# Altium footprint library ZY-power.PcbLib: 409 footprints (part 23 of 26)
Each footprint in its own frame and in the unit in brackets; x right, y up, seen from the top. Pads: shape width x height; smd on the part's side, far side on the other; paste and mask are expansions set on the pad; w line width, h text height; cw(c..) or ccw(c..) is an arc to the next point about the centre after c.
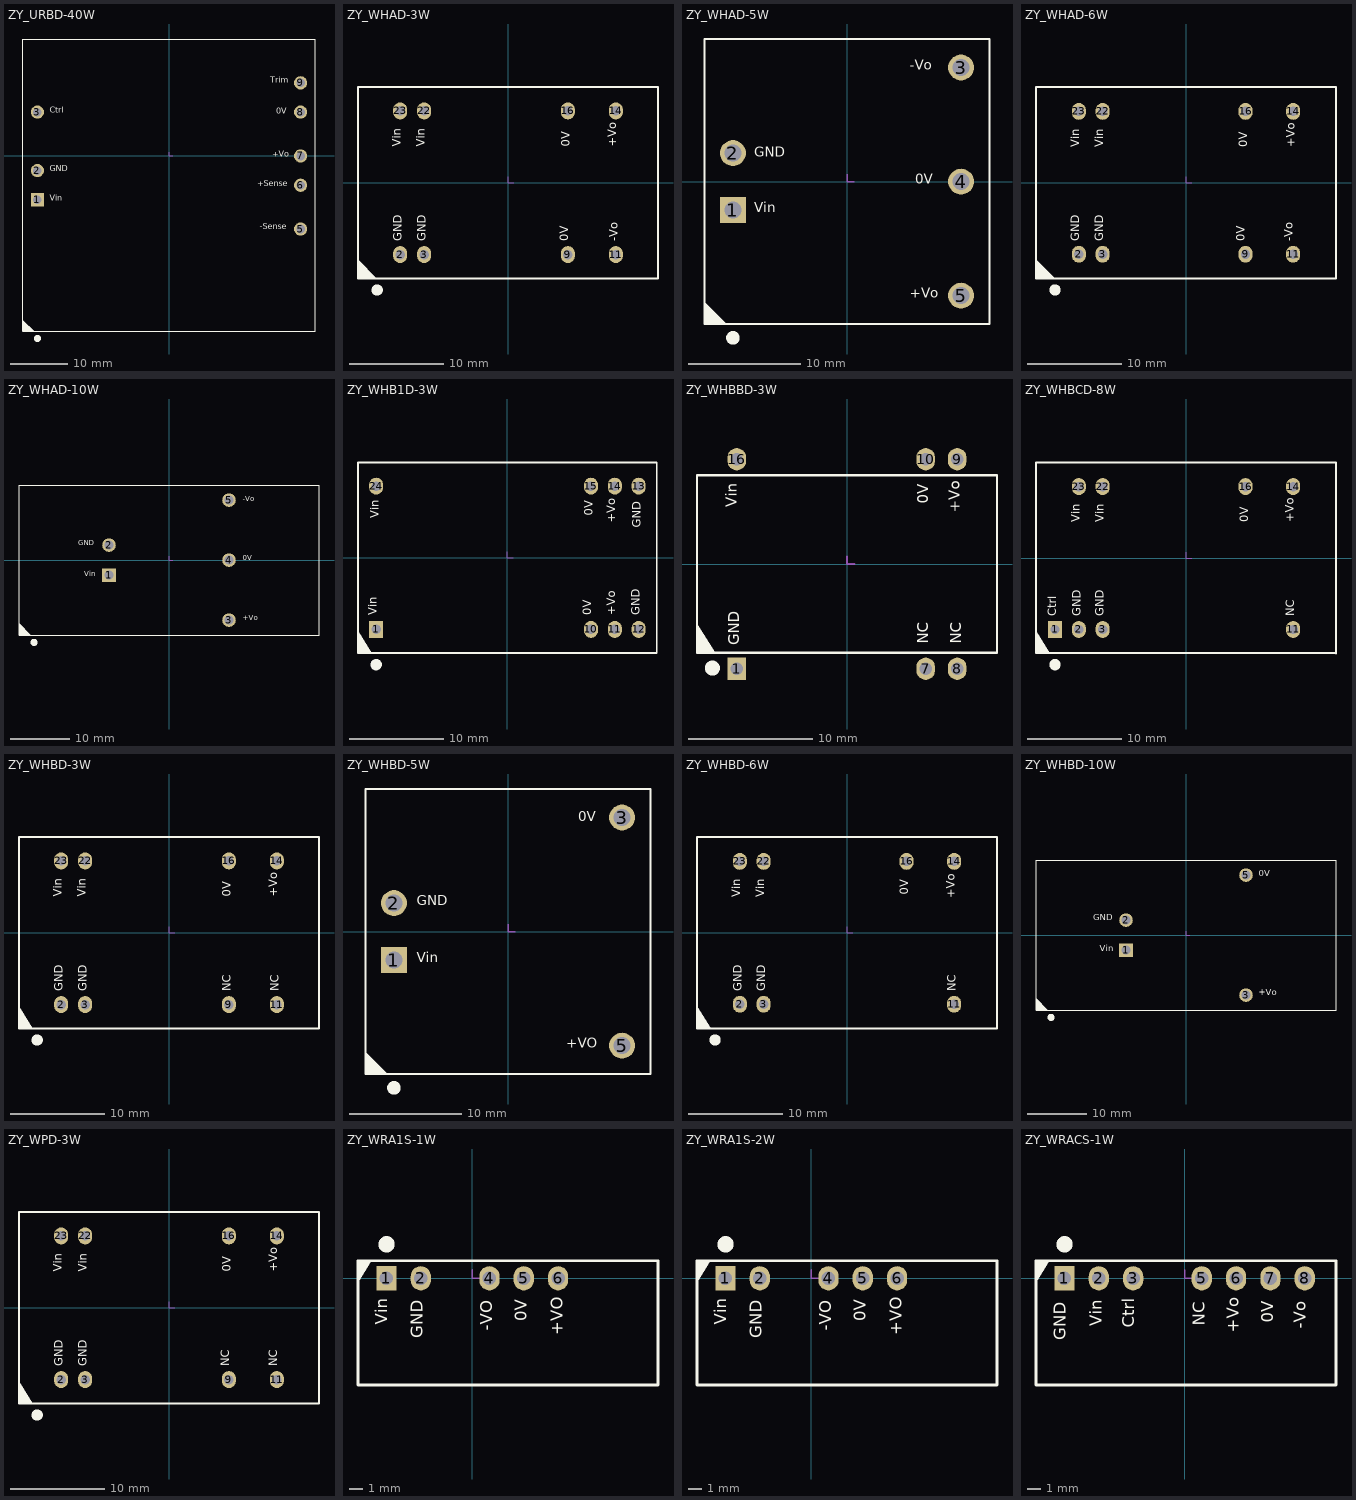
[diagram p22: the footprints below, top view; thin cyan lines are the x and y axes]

## ZY_URBD-40W [mm]
height 13.8
pads (8):
  rect 2.3x2.3 hole 1.5: 1(-22.86,-7.62)
  round 2.3 hole 1.5: 2(-22.86,-2.54) 3(-22.86,7.62) 5(22.86,-12.7) 6(22.86,-5.08) 7(22.86,0) 8(22.86,7.62) 9(22.86,12.7)
Top Overlay:
  circle w1: c-22.86,-31.705 r0.1
  region: -25.4,-30.48 -23.425,-30.48 -25.4,-28.505
  lines w0.2: -25.4,-30.48 -25.4,20.32 25.4,20.32 25.4,-30.48 -25.4,-30.48
  text "-Sense" at 15.731,-13.081 h1.78
  text "GND" at -20.701,-3.028 h1.78
  text "Trim" at 17.614,12.339 h1.78
  text "Ctrl" at -20.701,7.132 h1.78
  text "+Vo" at 17.926,-0.488 h1.78
  text "+Sense" at 15.367,-5.588 h1.78
  text "Vin" at -20.701,-8.108 h1.78
  text "0V" at 18.663,7.005 h1.78
Mechanical 15:
  lines w0.127: 0,0.635 0,0 0.635,0

## ZY_WHAD-3W [mm] "宽压输入隔离稳压双输出电源模块"
height 9.5
pads (8):
  oval 1.5x1.8 hole 1: 2(-11.43,-7.62) 3(-8.89,-7.62) 9(6.35,-7.62) 11(11.43,-7.62) 14(11.43,7.62) 16(6.35,7.62) 22(-8.89,7.62) 23(-11.43,7.62)
Top Overlay:
  circle w1: c-13.87,-11.375 r0.1
  region: -15.9,-10.15 -13.925,-10.15 -15.9,-8.175
  lines w0.2: -15.9,-10.15 15.9,-10.15 15.9,10.15 -15.9,10.15 -15.9,-10.15
  text "Vin" at -11.049,3.81 h1.52
  text "Vin" at -8.509,3.81 h1.52
  text "0V" at 6.858,3.81 h1.52
  text "+Vo" at 11.811,3.81 h1.52
  text "-Vo" at 11.938,-6.223 h1.52
  text "0V" at 6.731,-6.223 h1.52
  text "GND" at -8.382,-6.223 h1.52
  text "GND" at -10.922,-6.223 h1.52
Mechanical 15:
  lines w0.127: 0,0.635 0,0 0.635,0

## ZY_WHAD-5W [mm]
height 11.7
pads (5):
  rect 2.3x2.3 hole 1.5: 1(-10.16,-2.54)
  round 2.3 hole 1.5: 2(-10.16,2.54) 3(10.16,10.16) 4(10.16,0) 5(10.16,-10.16)
Top Overlay:
  circle w1: c-10.16,-13.925 r0.1
  region: -12.7,-12.7 -10.725,-12.7 -12.7,-10.725
  lines w0.2: -12.7,-12.7 -12.7,12.7 12.7,12.7 12.7,-12.7 -12.7,-12.7
  text "0V" at 6.096,-0.508 h1.52
  text "GND" at -8.255,1.905 h1.52
  text "Vin" at -8.255,-3.048 h1.52
  text "+Vo" at 5.588,-10.668 h1.52
  text "-Vo" at 5.588,9.652 h1.52
Mechanical 15:
  lines w0.127: 0,0.635 0,0 0.635,0

## ZY_WHAD-6W [mm]
height 10.5
pads (8):
  oval 1.5x1.8 hole 1: 2(-11.43,-7.62) 3(-8.89,-7.62) 9(6.35,-7.62) 11(11.43,-7.62) 14(11.43,7.62) 16(6.35,7.62) 22(-8.89,7.62) 23(-11.43,7.62)
Top Overlay:
  circle w1: c-13.97,-11.425 r0.1
  region: -16,-10.2 -14.025,-10.2 -16,-8.225
  lines w0.2: -16,-10.2 16,-10.2 16,10.2 -16,10.2 -16,-10.2
  text "0V" at 6.858,3.81 h1.52
  text "+Vo" at 11.938,3.81 h1.52
  text "-Vo" at 11.684,-6.223 h1.52
  text "Vin" at -8.509,3.81 h1.52
  text "Vin" at -11.049,3.81 h1.52
  text "GND" at -8.509,-6.223 h1.52
  text "GND" at -11.049,-6.223 h1.52
  text "0V" at 6.604,-6.223 h1.52
Mechanical 15:
  lines w0.127: 0,0.635 0,0 0.635,0

## ZY_WHAD-10W [mm]
pads (5):
  rect 2.3x2.3 hole 1.5: 1(-10.16,-2.54)
  round 2.3 hole 1.5: 2(-10.16,2.54) 3(10.16,-10.16) 4(10.16,0) 5(10.16,10.16)
Top Overlay:
  circle w1: c-22.86,-13.925 r0.1
  region: -25.4,-12.7 -23.425,-12.7 -25.4,-10.725
  lines w0.2: -25.4,-12.7 25.4,-12.7 25.4,12.7 -25.4,12.7 -25.4,-12.7
  text "Vin" at -14.358,-3.048 h1.52
  text "GND" at -15.368,2.159 h1.52
  text "0V" at 12.446,-0.381 h1.52
  text "+Vo" at 12.446,-10.541 h1.52
  text "-Vo" at 12.446,9.652 h1.52
Mechanical 15:
  lines w0.127: 0,0.635 0,0 0.635,0

## ZY_WHB1D-3W [mm]
height 10.5
pads (8):
  rect 1.5x1.8 hole 1: 1(-13.97,-7.62)
  oval 1.5x1.8 hole 1: 10(8.89,-7.62) 11(11.43,-7.62) 12(13.97,-7.62) 13(13.97,7.62) 14(11.43,7.62) 15(8.89,7.62) 24(-13.97,7.62)
Top Overlay:
  circle w1: c-13.97,-11.375 r0.1
  region: -15.9,-7.82 -15.9,-10.15 -14.44,-10.15
  lines w0.2: -15.9,-10.15 -15.9,10.15 15.9,10.15 15.9,-10.15 -15.9,-10.15
  text "GND" at 14.427,-6.096 h1.52
  text "Vin" at -13.36,4.185 h1.52
  text "Vin" at -13.564,-6.096 h1.52
  text "0V" at 9.246,-6.096 h1.52
  text "+Vo" at 11.811,-6.096 h1.52
  text "0V" at 9.423,4.457 h1.52
  text "+Vo" at 11.811,3.717 h1.52
  text "GND" at 14.503,3.175 h1.52
Mechanical 15:
  lines w0.127: 0,0.635 0,0 0.635,0

## ZY_WHBBD-3W [mm]
height 4.6
pads (6):
  rect 1.5x1.8 hole 1: 1(-8.89,-8.45)
  oval 1.5x1.8 hole 1: 7(6.35,-8.45) 8(8.89,-8.45) 9(8.89,8.45) 10(6.35,8.45) 16(-8.89,8.45)
Top Overlay:
  circle w1: c-10.863,-8.4 r0.1
  region: -12.1,-4.845 -12.1,-7.175 -10.64,-7.175
  lines w0.2: -12.1,-7.175 12.1,-7.175 12.1,7.175 -12.1,7.175 -12.1,-7.175
  text "NC" at 9.525,-6.415 h1.52
  text "GND" at -8.382,-6.542 h1.52
  text "Vin" at -8.56,4.597 h1.52
  text "0V" at 6.858,4.869 h1.52
  text "+Vo" at 9.398,4.129 h1.52
  text "NC" at 6.858,-6.415 h1.52
Mechanical 15:
  lines w0.127: 0,0.635 0,0 0.635,0

## ZY_WHBCD-8W [mm]
height 11
pads (8):
  rect 1.5x1.8 hole 1: 1(-13.97,-7.62)
  oval 1.5x1.8 hole 1: 2(-11.43,-7.62) 3(-8.89,-7.62) 11(11.43,-7.62) 14(11.43,7.62) 16(6.35,7.62) 22(-8.89,7.62) 23(-11.43,7.62)
Top Overlay:
  circle w1: c-13.97,-11.375 r0.1
  region: -16,-7.82 -16,-10.15 -14.54,-10.15
  lines w0.2: 16,-10.2 16,10.2 -16,10.2 -16,-10.15 16,-10.15
  text "GND" at -10.897,-6.223 h1.52
  text "+Vo" at 11.811,3.81 h1.52
  text "0V" at 6.985,3.81 h1.52
  text "Ctrl" at -13.538,-6.223 h1.52
  text "NC" at 11.887,-6.223 h1.52
  text "Vin" at -8.433,3.81 h1.52
  text "Vin" at -10.998,3.81 h1.52
  text "GND" at -8.458,-6.223 h1.52
Mechanical 15:
  lines w0.127: 0,0.635 0,0 0.635,0

## ZY_WHBD-3W [mm] "宽压输入隔离稳压单输出电源模块"
height 9.5
pads (8):
  oval 1.5x1.8 hole 1: 2(-11.43,-7.62) 3(-8.89,-7.62) 9(6.35,-7.62) 11(11.43,-7.62) 14(11.43,7.62) 16(6.35,7.62) 22(-8.89,7.62) 23(-11.43,7.62)
Top Overlay:
  circle w1: c-13.97,-11.375 r0.1
  region: -15.9,-7.82 -15.9,-10.15 -14.44,-10.15
  lines w0.2: -15.9,-10.15 15.9,-10.15 15.9,10.15 -15.9,10.15 -15.9,-10.15
  text "+Vo" at 11.811,3.81 h1.52
  text "0V" at 6.858,3.81 h1.52
  text "Vin" at -8.509,3.81 h1.52
  text "Vin" at -11.049,3.81 h1.52
  text "GND" at -8.382,-6.223 h1.52
  text "GND" at -10.922,-6.223 h1.52
  text "NC" at 6.858,-6.223 h1.52
  text "NC" at 11.938,-6.223 h1.52
Mechanical 15:
  lines w0.127: 0,0.635 0,0 0.635,0

## ZY_WHBD-5W [mm]
height 11.7
pads (4):
  rect 2.3x2.3 hole 1.5: 1(-10.16,-2.54)
  round 2.3 hole 1.5: 2(-10.16,2.54) 3(10.16,10.16) 5(10.16,-10.16)
Top Overlay:
  circle w1: c-10.16,-13.925 r0.1
  region: -12.7,-12.7 -10.725,-12.7 -12.7,-10.725
  lines w0.2: -12.7,-12.7 -12.7,12.7 12.7,12.7 12.7,-12.7 -12.7,-12.7
  text "GND" at -8.128,2.032 h1.52
  text "Vin" at -8.128,-3.048 h1.52
  text "+VO" at 5.207,-10.668 h1.52
  text "0V" at 6.238,9.525 h1.52
Mechanical 15:
  lines w0.127: 0,0.635 0,0 0.635,0

## ZY_WHBD-6W [mm]
height 10.5
pads (7):
  oval 1.5x1.8 hole 1: 2(-11.43,-7.62) 3(-8.89,-7.62) 11(11.43,-7.62) 14(11.43,7.62) 16(6.35,7.62) 22(-8.89,7.62) 23(-11.43,7.62)
Top Overlay:
  circle w1: c-14.07,-11.425 r0.1
  region: -16,-7.87 -16,-10.2 -14.54,-10.2
  lines w0.2: -16,-10.2 16,-10.2 16,10.2 -16,10.2 -16,-10.2
  text "0V" at 6.858,4.064 h1.52
  text "+Vo" at 11.811,3.683 h1.52
  text "NC" at 11.938,-6.223 h1.52
  text "Vin" at -8.509,3.81 h1.52
  text "Vin" at -11.049,3.81 h1.52
  text "GND" at -8.382,-6.223 h1.52
  text "GND" at -10.922,-6.223 h1.52
Mechanical 15:
  lines w0.127: 0,0.635 0,0 0.635,0

## ZY_WHBD-10W [mm]
pads (4):
  rect 2.3x2.3 hole 1.5: 1(-10.16,-2.54)
  round 2.3 hole 1.5: 2(-10.16,2.54) 3(10.16,-10.16) 5(10.16,10.16)
Top Overlay:
  circle w1: c-22.86,-13.925 r0.1
  region: -25.4,-12.7 -23.425,-12.7 -25.4,-10.725
  lines w0.2: -25.4,-12.7 -25.4,12.7 25.4,12.7 25.4,-12.7 -25.4,-12.7
  text "+Vo" at 12.319,-10.541 h1.78
  text "0V" at 12.319,9.652 h1.78
  text "GND" at -15.748,2.159 h1.78
  text "Vin" at -14.568,-3.048 h1.78
Mechanical 15:
  lines w0.127: 0,0.635 0,0 0.635,0

## ZY_WPD-3W [mm] "宽压输入非隔离稳压单输出"
height 9.5
pads (8):
  oval 1.5x1.8 hole 1: 2(-11.43,-7.62) 3(-8.89,-7.62) 9(6.35,-7.62) 11(11.43,-7.62) 14(11.43,7.62) 16(6.35,7.62) 22(-8.89,7.62) 23(-11.43,7.62)
Top Overlay:
  circle w1: c-13.97,-11.375 r0.1
  region: -15.9,-7.82 -15.9,-10.15 -14.44,-10.15
  lines w0.2: -15.9,-10.15 15.9,-10.15 15.9,10.15 -15.9,10.15 -15.9,-10.15
  text "Vin" at -11.049,3.81 h1.52
  text "Vin" at -8.382,3.81 h1.52
  text "0V" at 6.858,3.81 h1.52
  text "+Vo" at 11.811,3.81 h1.52
  text "NC" at 11.811,-6.223 h1.52
  text "NC" at 6.731,-6.223 h1.52
  text "GND" at -8.382,-6.223 h1.52
  text "GND" at -10.922,-6.223 h1.52
Mechanical 15:
  lines w0.127: 0,0.635 0,0 0.635,0

## ZY_WRA1S-1W [mm]
height 12.2
pads (5):
  rect 1.5x1.8 hole 1: 1(-6.35,0)
  oval 1.5x1.8 hole 1: 2(-3.81,0) 4(1.27,0) 5(3.81,0) 6(6.35,0)
Top Overlay:
  circle w1: c-6.35,2.52 r0.1
  region: -8.458,-0.29 -8.458,1.295 -7.465,1.295
  lines w0.2: 13.741,-7.899 -8.458,-7.899 -8.458,1.295 13.741,1.295 13.741,-7.874
  text "-VO" at 1.778,-3.882 h1.52
  text "0V" at 4.343,-3.163 h1.52
  text "+VO" at 6.985,-4.194 h1.52
  text "Vin" at -5.994,-3.435 h1.52
  text "GND" at -3.353,-4.445 h1.52
Mechanical 15:
  lines w0.127: 0,0.635 0,0 0.635,0

## ZY_WRA1S-2W [mm]
height 12.2
pads (5):
  rect 1.5x1.8 hole 1: 1(-6.35,0)
  oval 1.5x1.8 hole 1: 2(-3.81,0) 4(1.27,0) 5(3.81,0) 6(6.35,0)
Top Overlay:
  circle w1: c-6.35,2.52 r0.1
  region: -8.458,-0.29 -8.458,1.295 -7.465,1.295
  lines w0.2: 13.741,-7.899 -8.458,-7.899 -8.458,1.295 13.741,1.295 13.741,-7.874
  text "-VO" at 1.778,-3.882 h1.52
  text "0V" at 4.343,-3.163 h1.52
  text "+VO" at 6.985,-4.194 h1.52
  text "Vin" at -5.994,-3.435 h1.52
  text "GND" at -3.353,-4.445 h1.52
Mechanical 15:
  lines w0.127: 0,0.635 0,0 0.635,0

## ZY_WRACS-1W [mm]
height 12.2
pads (7):
  rect 1.5x1.8 hole 1: 1(-8.89,0)
  oval 1.5x1.8 hole 1: 2(-6.35,0) 3(-3.81,0) 5(1.27,0) 6(3.81,0) 7(6.35,0) 8(8.89,0)
Top Overlay:
  circle w1: c-8.89,2.52 r0.1
  region: -10.998,-0.29 -10.998,1.295 -10.005,1.295
  lines w0.2: 11.201,-7.899 -10.998,-7.899 -10.998,1.295 11.201,1.295 11.201,-7.874
  text "GND" at -8.509,-4.572 h1.52
  text "Vin" at -5.842,-3.562 h1.52
  text "Ctrl" at -3.429,-3.646 h1.52
  text "NC" at 1.778,-3.501 h1.52
  text "+Vo" at 4.318,-4.03 h1.52
  text "0V" at 6.858,-3.29 h1.52
  text "-Vo" at 9.271,-3.718 h1.52
Mechanical 15:
  lines w0.127: 0,0.635 0,0 0.635,0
